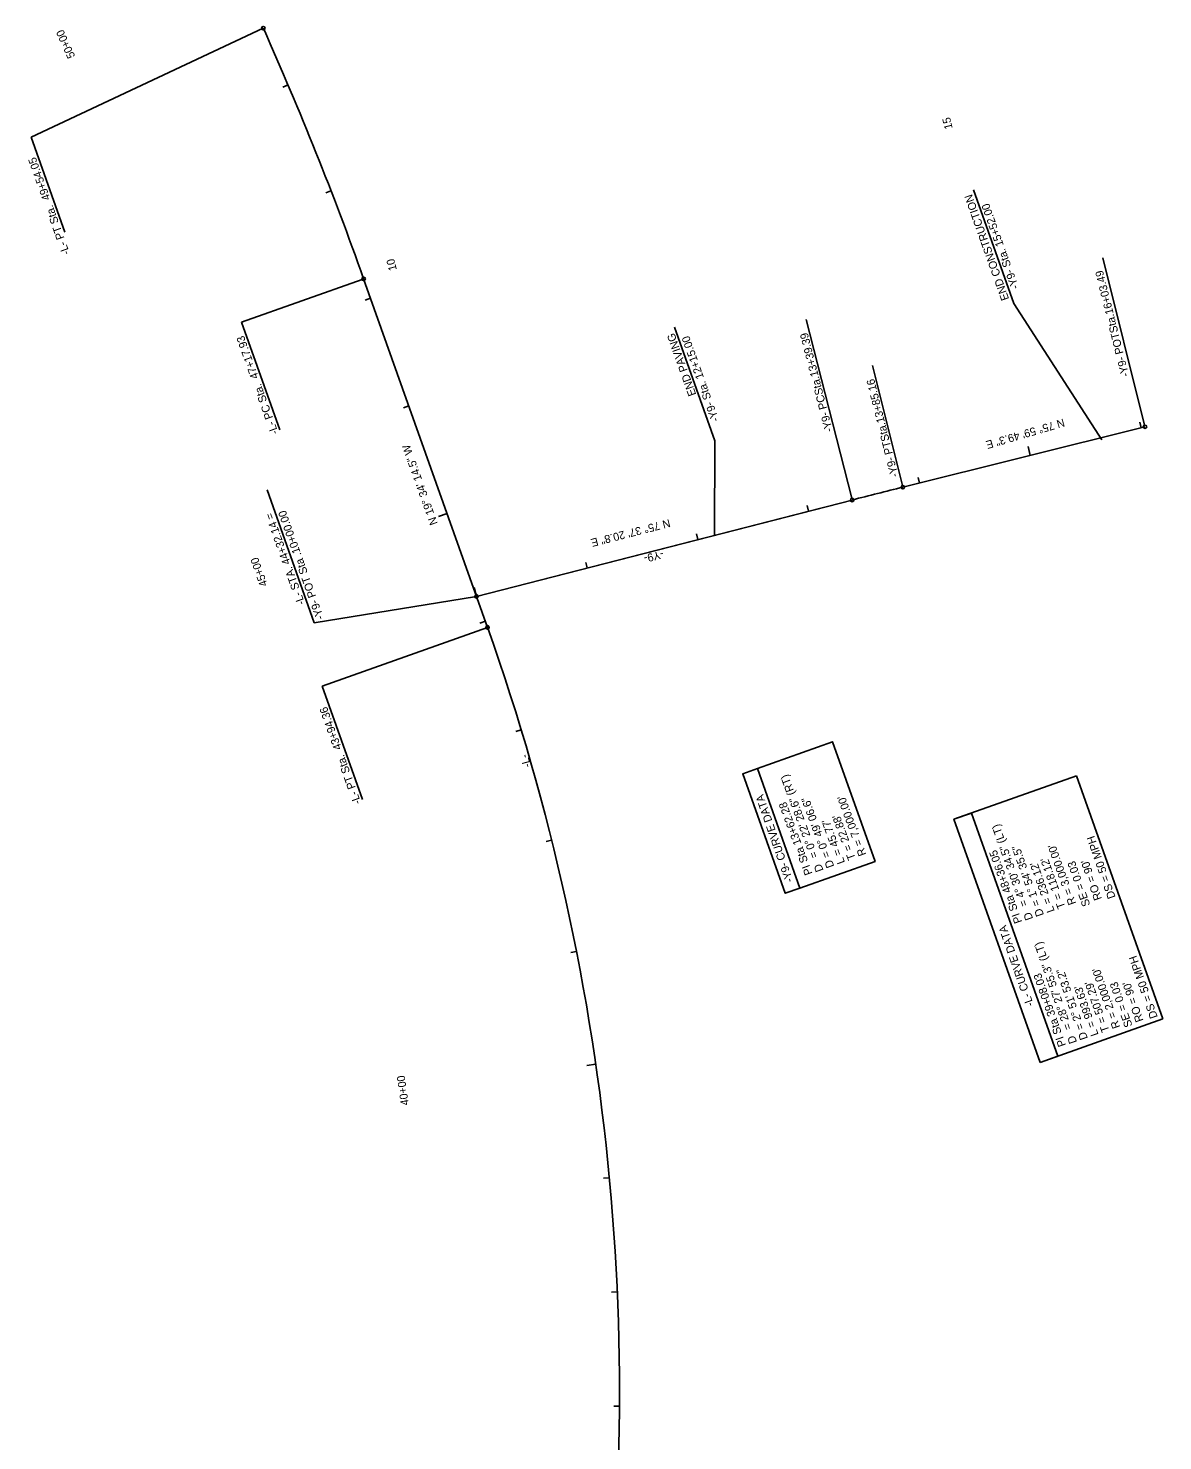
# Model space of a CAD drawing. Extents: x 1615712 to 1617175, y 899615 to 904865.
# Drawn here: x 1616182 to 1617175, y 902243 to 903479 of the extents above; entities that cross this region are included whole.
import ezdxf

# ---------------------------------------------------------------- set-up
doc = ezdxf.new("R2010")
doc.units = 0
for name, color, linetype in [('Prop Horizontal Alignment', 7, 'Continuous'), ('Prop Horizontal Alignment Curve and Spiral Data', 7, 'Continuous'), ('Prop Horizontal Alignment Direction Label', 7, 'Continuous'), ('Prop Horizontal Alignment Station Label', 7, 'Continuous'), ('Prop Horizontal Alignment Tick Label', 7, 'Continuous'), ('Prop Horizontal Alignment Tick Large', 7, 'Continuous'), ('Prop Horizontal Alignment Tick Small', 7, 'Continuous'), ('Scratch_Level_0', 7, 'Continuous')]:
    doc.layers.add(name, color=color, linetype=linetype)

msp = doc.modelspace()

# ---------------------------------------------------------------- linework, layer by layer
at = {"layer": 'Prop Horizontal Alignment'}
for p, q in [((1616584.1, 902954.6), (1616475.7, 903259.5)), ((1616584.1, 902954.6), (1616475.7, 903259.5)), ((1616947.6, 903077.2), (1617159.4, 903130.1)), ((1616574.4, 902981.7), (1616903.2, 903066)), ((1616574.4, 902981.7), (1616875.8, 903059))]:
    msp.add_line(p, q, dxfattribs=at)
for centre, radius, start, end in [((1613649, 902254.6), 3000, 19.5707, 24.0803), ((1613649, 902254.6), 3000, 19.5707, 24.0803), ((1618641.4, 896285.3), 7000, 104.00296, 104.37756), ((1614699.6, 902284.7), 2000, 351.1053, 19.5707), ((1614699.6, 902284.7), 2000, 351.1053, 19.5707)]:
    msp.add_arc(centre, radius, start, end, dxfattribs=at)
at = {"layer": 'Prop Horizontal Alignment Curve and Spiral Data'}
for p, q in [((1616184.6, 903383.4), (1616387.9, 903478.7)), ((1616368.9, 903221.5), (1616474.3, 903259)), ((1616574.4, 902981.7), (1616432.5, 902958.7)), ((1616584.1, 902954.6), (1616439.3, 902903.2)), ((1616992.2, 902786.7), (1617099.4, 902824.8)), ((1617099.4, 902824.8), (1617175, 902612.1)), ((1617067.8, 902574), (1616992.2, 902786.7)), ((1617175, 902612.1), (1617067.8, 902574))]:
    msp.add_line(p, q, dxfattribs=at)
for points in [[(1616857.4, 902726.5), (1616820.2, 902831.1), (1616886.1, 902854.5), (1616923.3, 902749.9)], [(1616857.4, 902726.5), (1616820.2, 902831.1), (1616807.5, 902826.6), (1616844.6, 902722)], [(1617067.8, 902574), (1616992.2, 902786.7), (1617007.7, 902792.2), (1617083.3, 902579.5)]]:
    msp.add_lwpolyline(points, close=True, dxfattribs=at)
at = {"layer": 'Prop Horizontal Alignment Station Label'}
for p, q in [((1616214.2, 903300.2), (1616184.6, 903383.4)), ((1617044.7, 903237.8), (1617009.4, 903337.3)), ((1617159.1, 903131.5), (1617122.6, 903277.8)), ((1616584.1, 902954.6), (1616475.7, 903259.5)), ((1616584.1, 902954.6), (1616475.7, 903259.5)), ((1616584.1, 902954.6), (1616475.7, 903259.5)), ((1617044.7, 903237.8), (1617121.8, 903118.6)), ((1616402.4, 903127.4), (1616368.9, 903221.5)), ((1616783.1, 903117.9), (1616747.8, 903217.3)), ((1616902.8, 903067.5), (1616862.8, 903223.8)), ((1616947.2, 903078.7), (1616921, 903183.6)), ((1616782.7, 903035.1), (1616783.1, 903117.9)), ((1616432.5, 902958.7), (1616391.3, 903074.8)), ((1616474.6, 902804), (1616439.3, 902903.2))]:
    msp.add_line(p, q, dxfattribs=at)
for centre in [(1616387.9, 903478.7), (1616475.7, 903259.5), (1617159.4, 903130.1), (1616947.6, 903077.2), (1616903.2, 903066), (1616574.4, 902981.7), (1616574.4, 902981.7), (1616584.1, 902954.6)]:
    msp.add_circle(centre, 1.5, dxfattribs=at)
for centre, radius, start, end in [((1613649, 902254.6), 3000, 19.5707, 24.0803), ((1613649, 902254.6), 3000, 19.5707, 24.0803), ((1613649, 902254.6), 3000, 19.5707, 24.0803), ((1614699.6, 902284.7), 2000, 351.1053, 19.5707), ((1614699.6, 902284.7), 2000, 351.1053, 19.5707), ((1614699.6, 902284.7), 2000, 351.1053, 19.5707)]:
    msp.add_arc(centre, radius, start, end, dxfattribs=at)
at = {"layer": 'Prop Horizontal Alignment Tick Large'}
for p, q in [((1617059, 903105), (1617057.1, 903112.8)), ((1616548.7, 903054.2), (1616541.2, 903051.5)), ((1616574.4, 902981.7), (1616572.5, 902989.5)), ((1616574.4, 902981.7), (1616572.5, 902989.5)), ((1616678.8, 902572.5), (1616670.9, 902571.3))]:
    msp.add_line(p, q, dxfattribs=at)
at = {"layer": 'Prop Horizontal Alignment Tick Small'}
for p, q in [((1616409.5, 903429.1), (1616404.9, 903427.2)), ((1616447.1, 903336.5), (1616442.5, 903334.7)), ((1616481.7, 903242.6), (1616477, 903240.9)), ((1616515.2, 903148.4), (1616510.5, 903146.7)), ((1617156, 903129.2), (1617154.8, 903134.1)), ((1616962, 903080.8), (1616960.8, 903085.7)), ((1616865, 903056.2), (1616863.8, 903061.1)), ((1616865, 903056.2), (1616863.8, 903061.1)), ((1616768.2, 903031.4), (1616766.9, 903036.3)), ((1616768.2, 903031.4), (1616766.9, 903036.3)), ((1616671.3, 903006.6), (1616670.1, 903011.4)), ((1616671.3, 903006.6), (1616670.1, 903011.4)), ((1616582.2, 902960), (1616577.5, 902958.3)), ((1616613.6, 902865), (1616608.8, 902863.6)), ((1616640.2, 902768.6), (1616635.3, 902767.4)), ((1616662, 902671), (1616657, 902670.1)), ((1616690.7, 902473.2), (1616685.7, 902472.7)), ((1616697.6, 902373.5), (1616692.7, 902373.2)), ((1616699.6, 902273.5), (1616694.6, 902273.5))]:
    msp.add_line(p, q, dxfattribs=at)
at = {"layer": 'Scratch_Level_0'}
msp.add_line((1616584.1, 902954.6), (1616475.7, 903259.5), dxfattribs=at)
msp.add_line((1616584.1, 902954.6), (1616475.7, 903259.5), dxfattribs=at)
for centre, radius, start, end in [((1613649, 902254.6), 3000, 19.5707, 24.0803), ((1613649, 902254.6), 3000, 19.5707, 24.0803), ((1614699.6, 902284.7), 2000, 351.1053, 19.5707), ((1614699.6, 902284.7), 2000, 351.1053, 19.5707)]:
    msp.add_arc(centre, radius, start, end, dxfattribs=at)

# ---------------------------------------------------------------- texts
at = {"layer": 'Prop Horizontal Alignment Curve and Spiral Data'}
for s, rotation, p in [('= 0%%d 22\' 28.6" (RT)', 110.2158, (1616873.5, 902754.1)), ('-Y9- CURVE DATA', 109.2037, (1616851.7, 902732.9)), ("R = 7,000.00'", 110.2158, (1616915.7, 902756)), ('PI Sta 13+62.28', 110.2158, (1616868.6, 902739.3)), ('D = 0%%d 49\' 06.6"', 110.2158, (1616887.6, 902745.6)), ("L = 45.77'", 110.2158, (1616897, 902749)), ("T = 22.88'", 110.2158, (1616906.4, 902752.5)), ('= 4%%d 30\' 34.5" (LT)', 109.5707, (1617057.1, 902711.8)), ('DS = 50 MPH', 109.2037, (1617133.8, 902718.6)), ('PI Sta 48+36.05', 109.5707, (1617052, 902697)), ('D = 1%%d 54\' 35.5"', 109.5707, (1617071.1, 902703.1)), ("R = 3,000.00'", 109.5707, (1617099.3, 902713.2)), ('D', 110.2158, (1616878.2, 902742.1)), ("L = 236.12'", 109.5707, (1617080.5, 902706.5)), ("T = 118.12'", 109.5707, (1617089.9, 902709.8)), ('SE = 0.03', 109.2037, (1617111.6, 902711.8)), ("RO = 90'", 109.2037, (1617121.8, 902717.2)), ('-L- CURVE DATA', 109.2037, (1617062.2, 902624.4)), ('D', 109.5707, (1617061.6, 902699.8)), ('= 28%%d 27\' 55.3" (LT)', 109.2037, (1617095.5, 902603.8)), ('DS = 50 MPH', 109.2037, (1617170.7, 902613.8)), ('PI Sta 39+08.03', 109.2037, (1617090.4, 902589.1)), ('D = 2%%d 51\' 53.2"', 109.2037, (1617109.5, 902595.1)), ("R = 2,000.00'", 109.2037, (1617137.8, 902605)), ("L = 993.63'", 109.2037, (1617118.9, 902598.4)), ("T = 507.29'", 109.2037, (1617128.4, 902601.7)), ('SE = 0.03', 109.2037, (1617148.6, 902606.1)), ("RO = 90'", 109.2037, (1617158.2, 902610.7)), ('D', 109.2037, (1617100, 902591.8))]:
    msp.add_text(s, height=7, rotation=rotation, dxfattribs=at).set_placement(p)
at = {"layer": 'Prop Horizontal Alignment Direction Label'}
for s, rotation, p in [('N 75%%d 59\' 49.3" E', 196.3537, (1617087.9, 903137.3)), ('N 19%%d 34\' 14.5" W', 109.5707, (1616540.6, 903045.5)), ('N 75%%d 37\' 20.8" E', 194.3996, (1616743, 903049.4))]:
    msp.add_text(s, height=7, rotation=rotation, dxfattribs=at).set_placement(p)
at = {"layer": 'Prop Horizontal Alignment Station Label'}
for s, rotation, p in [('-L- PT Sta.  49+54.05', 109.5707, (1616218.6, 903281.9)), ('END CONSTRUCTION', 109.5707, (1617040.6, 903241.9)), ('-Y9- Sta. 15+52.00', 109.5707, (1617049.2, 903251.8)), ('-Y9- POTSta.16+03.49', 104.003, (1617145.6, 903174.7)), ('-L- PC Sta.  47+17.93', 109.5707, (1616401.2, 903124.7)), ('END PAVING', 109.5707, (1616766.8, 903158.3)), ('-Y9- Sta. 12+15.00', 109.5707, (1616786.8, 903135.9)), ('-Y9- PCSta.13+39.39', 104.3776, (1616886.3, 903126.4)), ('-Y9- PTSta.13+85.16', 104.003, (1616943.7, 903086.9)), ('-L- STA. 44+32.14 =', 109.5707, (1616424.4, 902975.5)), ('-Y9- POT Sta .10+00.00', 109.5707, (1616441, 902962.7)), ('-L- PT Sta.  43+94.36', 109.5707, (1616473.5, 902801.2))]:
    msp.add_text(s, height=7, rotation=rotation, dxfattribs=at).set_placement(p)
at = {"layer": 'Prop Horizontal Alignment Tick Label'}
for s, rotation, p in [('50+00', 114.0803, (1616223.4, 903454.1)), ('15', 104.003, (1616991.2, 903391.2)), ('10', 104.3776, (1616504.8, 903267.5)), ('-Y9-', 194.0831, (1616737.4, 903022.1)), ('45+00', 109.5707, (1616391.8, 902991.7)), ('-L-', 104.6799, (1616622.1, 902833.1)), ('40+00', 98.273, (1616515.3, 902537))]:
    msp.add_text(s, height=7, rotation=rotation, dxfattribs=at).set_placement(p)

doc.saveas('drawing.dxf')
